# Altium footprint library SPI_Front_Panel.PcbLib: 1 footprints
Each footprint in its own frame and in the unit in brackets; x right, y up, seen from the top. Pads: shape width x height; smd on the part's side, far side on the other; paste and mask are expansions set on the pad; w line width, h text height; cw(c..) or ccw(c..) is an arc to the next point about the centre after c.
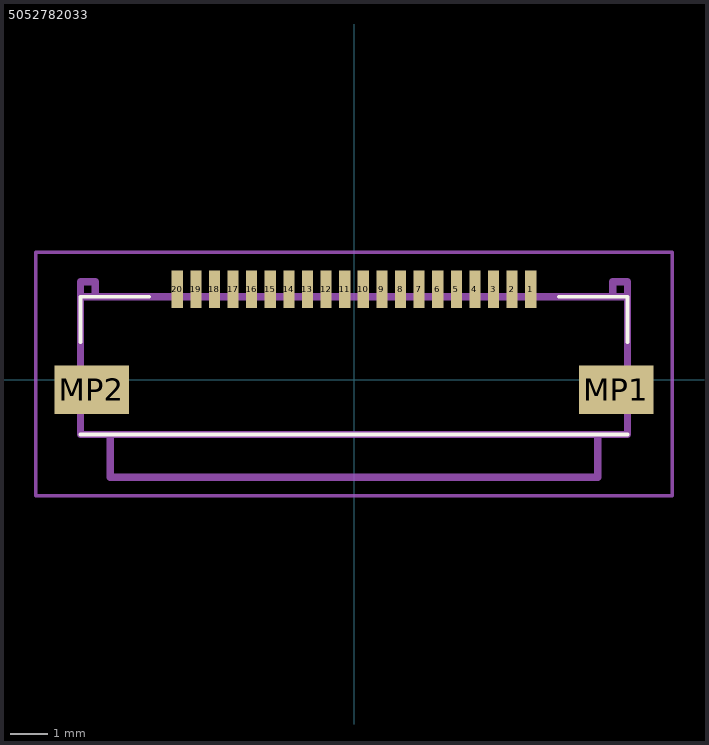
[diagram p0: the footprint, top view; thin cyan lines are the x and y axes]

## 5052782033 [mm]
pads (22):
  rect 0.3x1 smd: 1(4.75,2.425) 2(4.25,2.425) 3(3.75,2.425) 4(3.25,2.425) 5(2.75,2.425) 6(2.25,2.425) 7(1.75,2.425) 8(1.25,2.425) 9(0.75,2.425) 10(0.25,2.425) 11(-0.25,2.425) 12(-0.75,2.425) 13(-1.25,2.425) 14(-1.75,2.425) 15(-2.25,2.425) 16(-2.75,2.425) 17(-3.25,2.425) 18(-3.75,2.425) 19(-4.25,2.425) 20(-4.75,2.425)
  rect 2x1.3 smd: MP1(7.05,-0.275) MP2(-7.05,-0.275)
Top Overlay:
  lines w0.1: -7.35,-1.475 7.35,-1.475 ; -7.35,1 -7.35,2.225 -5.5,2.225 ; 5.5,2.225 7.35,2.225 7.35,1
Mechanical 13:
  lines w0.2: -7.35,2.225 -7.35,2.625 -6.95,2.625 -6.95,2.225 -7.35,2.225 ; -7.35,2.225 -7.35,-1.475 7.35,-1.475 7.35,2.225 ; -7.35,2.225 7.35,2.225 ; 7.35,2.225 7.35,2.625 6.95,2.625 6.95,2.225 7.35,2.225 ; -6.55,-2.625 -6.55,-1.475 6.55,-1.475 6.55,-2.625 -6.55,-2.625
Mechanical 15:
  lines w0.1: -8.55,-3.125 -8.55,3.425 8.55,3.425 8.55,-3.125 -8.55,-3.125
